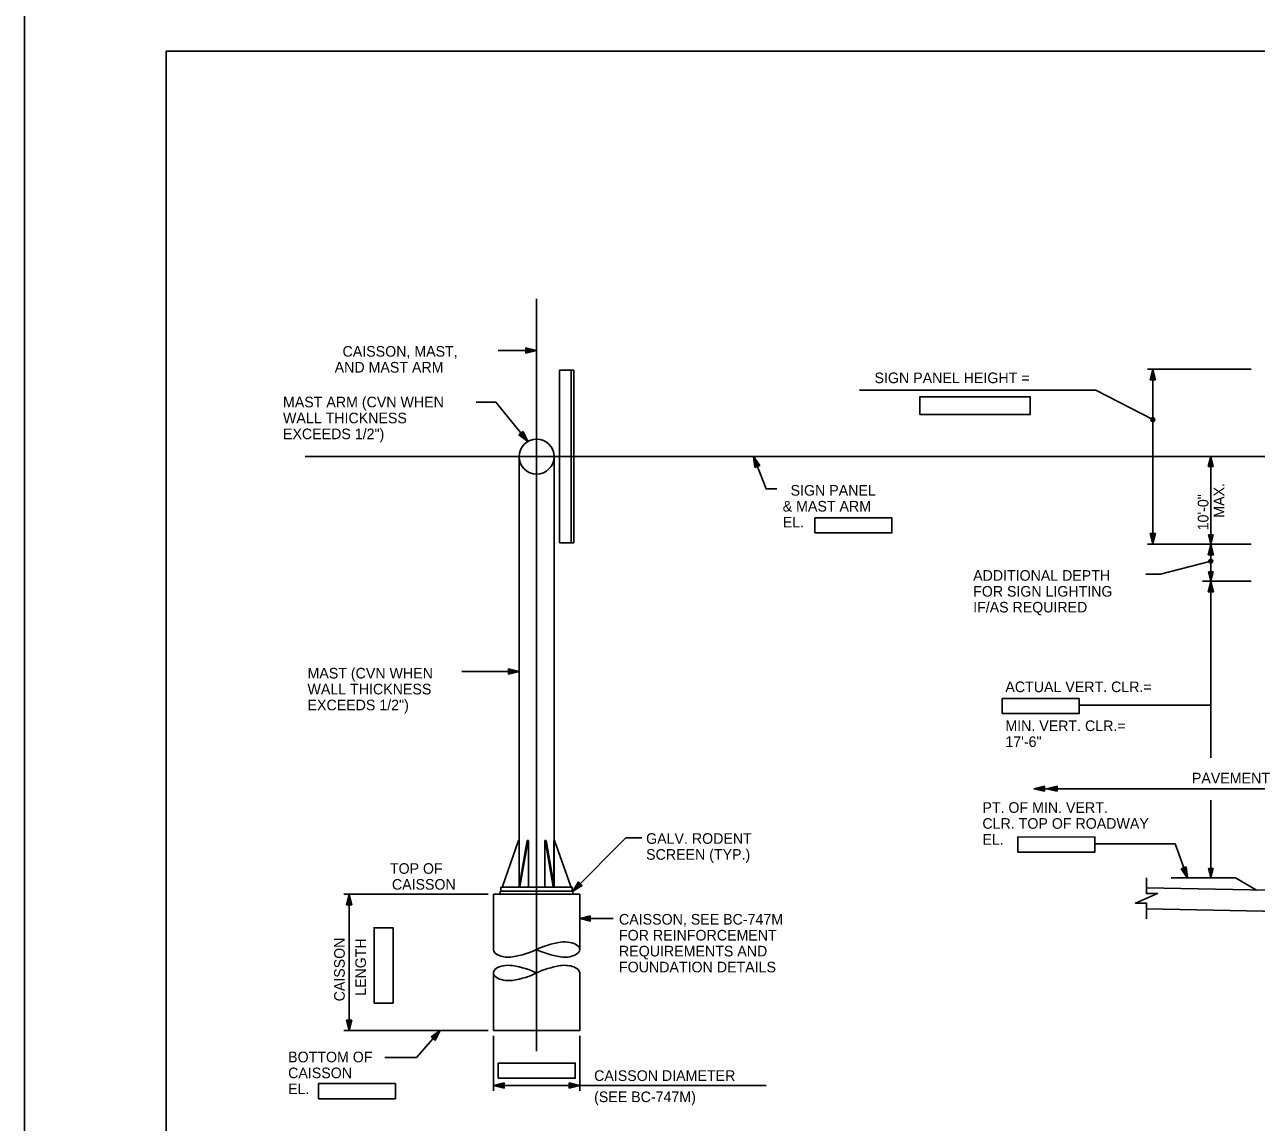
# Model space of a CAD drawing. Extents: x 640117 to 642655, y 297247 to 298435.
# Drawn here: x 640117.5 to 640465.5, y 297523.7 to 297834 of the extents above; entities that cross this region are included whole.
import ezdxf

# ---------------------------------------------------------------- set-up
doc = ezdxf.new("R2010")
doc.units = 0
for name, color, linetype in [('10', 7, 'Continuous'), ('2', 7, 'Continuous'), ('25', 7, 'Continuous'), ('49', 7, 'Continuous'), ('50', 7, 'Continuous'), ('51', 7, 'Continuous'), ('52', 7, 'Continuous'), ('55', 7, 'Continuous'), ('PLT-BNDY', 7, 'Continuous')]:
    doc.layers.add(name, color=color, linetype=linetype)

msp = doc.modelspace()

# ---------------------------------------------------------------- linework, layer by layer
at = {"layer": '10'}
for p, q in [((640452.64, 297711.85), (640452.63, 297626.7)), ((640451.97, 297689.76), (640452.63, 297687.11)), ((640453.3, 297689.76), (640451.97, 297689.76)), ((640452.17, 297689.6), (640452.63, 297687.76)), ((640453.1, 297689.6), (640452.17, 297689.6)), ((640452.37, 297689.44), (640452.63, 297688.41)), ((640452.89, 297689.44), (640452.37, 297689.44)), ((640452.55, 297689.38), (640452.63, 297689.05)), ((640452.63, 297687.11), (640453.3, 297689.76)), ((640452.63, 297687.76), (640453.1, 297689.6)), ((640452.63, 297688.41), (640452.89, 297689.44)), ((640452.63, 297689.05), (640452.71, 297689.37)), ((640451.97, 297679.28), (640452.63, 297676.63)), ((640453.3, 297679.28), (640451.97, 297679.28)), ((640452.17, 297679.12), (640452.63, 297677.28)), ((640453.1, 297679.12), (640452.17, 297679.12)), ((640452.37, 297678.96), (640452.63, 297677.92)), ((640452.89, 297678.96), (640452.37, 297678.96)), ((640452.55, 297678.9), (640452.63, 297678.57)), ((640452.63, 297676.63), (640453.3, 297679.28)), ((640452.63, 297677.28), (640453.1, 297679.12)), ((640452.63, 297677.92), (640452.89, 297678.96)), ((640452.63, 297678.57), (640452.71, 297678.88)), ((640452.63, 297641.63), (640415.43, 297641.63)), ((640452.63, 297614.72), (640452.63, 297592.74)), ((640445.7, 297595.86), (640444.27, 297595.34)), ((640444.27, 297595.34), (640446.02, 297592.74)), ((640445.55, 297595.61), (640444.55, 297595.25)), ((640444.55, 297595.25), (640445.77, 297593.44)), ((640445.39, 297595.36), (640444.83, 297595.16)), ((640444.83, 297595.16), (640445.52, 297594.14)), ((640445.05, 297595.16), (640445.26, 297594.84)), ((640445.26, 297594.84), (640445.23, 297595.21)), ((640445.52, 297594.14), (640445.39, 297595.36)), ((640445.77, 297593.44), (640445.55, 297595.61)), ((640446.02, 297592.74), (640445.7, 297595.86)), ((640451.97, 297595.39), (640452.63, 297592.74)), ((640453.29, 297595.39), (640451.97, 297595.39)), ((640452.17, 297595.23), (640452.63, 297593.39)), ((640453.09, 297595.23), (640452.17, 297595.23)), ((640452.37, 297595.07), (640452.63, 297594.03)), ((640452.89, 297595.07), (640452.37, 297595.07)), ((640452.55, 297595.01), (640452.63, 297594.68)), ((640452.63, 297592.74), (640453.29, 297595.39)), ((640452.63, 297593.39), (640453.09, 297595.23)), ((640452.63, 297594.03), (640452.89, 297595.07)), ((640452.63, 297594.68), (640452.71, 297594.99))]:
    msp.add_line(p, q, dxfattribs=at)
for points in [[(640446.02, 297592.74), (640442.53, 297602.41), (640419.7, 297602.41)], [(640441.45, 297592.74), (640459.58, 297592.74), (640465.5, 297589.31)]]:
    msp.add_lwpolyline(points, dxfattribs=at)
msp.add_lwpolyline([(640216.21, 297557.37), (640221.58, 297557.37), (640221.58, 297578.69), (640216.21, 297578.69)], close=True, dxfattribs=at)
at = {"layer": '2'}
for p, q in [((640157.46, 297262.46), (640157.46, 297826.46)), ((640157.46, 297826.46), (640943.46, 297826.46))]:
    msp.add_line(p, q, dxfattribs=at)
for points in [[(640370.43, 297723.77), (640401.59, 297723.77), (640401.59, 297728.75), (640370.43, 297728.75)], [(640340.78, 297690.26), (640362.53, 297690.26), (640362.53, 297694.51), (640340.78, 297694.51)], [(640393.68, 297639.22), (640415.43, 297639.22), (640415.43, 297643.47), (640393.68, 297643.47)], [(640398.13, 297600.08), (640419.88, 297600.07), (640419.88, 297604.32), (640398.13, 297604.33)], [(640251.3, 297536.15), (640273.05, 297536.14), (640273.05, 297540.39), (640251.3, 297540.4)], [(640200.47, 297530.35), (640222.22, 297530.35), (640222.22, 297534.6), (640200.47, 297534.6)]]:
    msp.add_lwpolyline(points, close=True, dxfattribs=at)
at = {"layer": '25'}
msp.add_line((640434.45, 297589.93), (640509.69, 297588.43), dxfattribs=at)
msp.add_lwpolyline([(640434.45, 297584.03), (640509.69, 297582.52)], dxfattribs=at)
at = {"layer": '49'}
for p, q in [((640268.61, 297687.47), (640268.61, 297736.24)), ((640268.61, 297736.24), (640272.67, 297736.24)), ((640271.86, 297687.47), (640271.86, 297736.24)), ((640272.67, 297687.47), (640272.67, 297736.24)), ((640268.61, 297687.47), (640272.67, 297687.47))]:
    msp.add_line(p, q, dxfattribs=at)
at = {"layer": '50'}
for p, q in [((640262.11, 297543.75), (640262.11, 297756.48)), ((640196.72, 297711.85), (640710.96, 297711.85))]:
    msp.add_line(p, q, dxfattribs=at)
at = {"layer": '51'}
for p, q in [((640249.91, 297588.17), (640274.3, 297588.17)), ((640249.91, 297572.51), (640249.91, 297588.17)), ((640274.3, 297572.51), (640274.3, 297588.17)), ((640249.91, 297549.58), (640249.91, 297565.89)), ((640274.3, 297549.58), (640274.3, 297565.89)), ((640249.91, 297549.58), (640274.3, 297549.58))]:
    msp.add_line(p, q, dxfattribs=at)
for centre, major_axis, start_param, end_param in [((640274.3, 297566.42), (17.24, 0), 1.89032, 2.356194), ((640269.98, 297572.51), (4.32, 0), 4.455588, 8.110783), ((640254.23, 297572.51), (-4.32, 0), 0, 1.827597), ((640249.91, 297578.61), (-17.24, 0), 1.89032, 2.356194), ((640274.3, 297578.61), (17.24, 0), 3.926991, 4.392865), ((640254.23, 297565.89), (-4.32, 0), 4.455588, 8.110783), ((640249.91, 297559.79), (-17.24, 0), 3.926991, 4.392865), ((640274.3, 297559.79), (17.24, 0), 1.89032, 2.356194), ((640269.98, 297565.89), (4.32, 0), 0, 1.827597), ((640249.91, 297571.98), (-17.24, 0), 1.89032, 2.356194)]:
    msp.add_ellipse(centre, major_axis=major_axis, ratio=0.5, start_param=start_param, end_param=end_param, dxfattribs=at)
at = {"layer": '52'}
for p, q in [((640262.11, 297741.87), (640259.11, 297742.62)), ((640259.11, 297742.62), (640259.11, 297741.12)), ((640259.11, 297741.12), (640262.11, 297741.87)), ((640261.37, 297741.87), (640259.28, 297742.39)), ((640259.28, 297742.39), (640259.28, 297741.35)), ((640259.28, 297741.35), (640261.37, 297741.87)), ((640260.64, 297741.87), (640259.46, 297742.16)), ((640259.46, 297742.16), (640259.46, 297741.57)), ((640259.46, 297741.57), (640260.64, 297741.87)), ((640259.53, 297741.78), (640259.91, 297741.87)), ((640259.91, 297741.87), (640259.55, 297741.96)), ((640464, 297736.59), (640434.76, 297736.59)), ((640436.26, 297736.59), (640435.51, 297733.59)), ((640435.51, 297733.59), (640437.01, 297733.59)), ((640436.26, 297735.85), (640435.73, 297733.76)), ((640435.73, 297733.76), (640436.78, 297733.76)), ((640436.26, 297735.12), (640435.96, 297733.94)), ((640435.96, 297733.94), (640436.55, 297733.94)), ((640436.26, 297734.39), (640436.17, 297734.03)), ((640436.26, 297687.12), (640436.26, 297736.59)), ((640437.01, 297733.59), (640436.26, 297736.59)), ((640436.78, 297733.76), (640436.26, 297735.85)), ((640436.55, 297733.94), (640436.26, 297735.12)), ((640436.35, 297734.01), (640436.26, 297734.39)), ((640258.3, 297718.92), (640257.13, 297717.98)), ((640257.13, 297717.98), (640259.6, 297716.12)), ((640258.23, 297718.64), (640257.42, 297717.98)), ((640257.42, 297717.98), (640259.14, 297716.69)), ((640258.17, 297718.36), (640257.71, 297717.99)), ((640257.71, 297717.99), (640258.68, 297717.26)), ((640257.91, 297718.06), (640258.22, 297717.83)), ((640258.22, 297717.83), (640258.06, 297718.16)), ((640258.68, 297717.26), (640258.17, 297718.36)), ((640259.14, 297716.69), (640258.23, 297718.64)), ((640259.6, 297716.12), (640258.3, 297718.92)), ((640323.41, 297711.85), (640325.2, 297709.32)), ((640323.8, 297708.78), (640323.41, 297711.85)), ((640323.68, 297711.17), (640324.92, 297709.41)), ((640323.95, 297709.03), (640323.68, 297711.17)), ((640325.2, 297709.32), (640323.8, 297708.78)), ((640324.09, 297709.28), (640323.94, 297710.48)), ((640323.94, 297710.48), (640324.64, 297709.49)), ((640324.92, 297709.41), (640323.95, 297709.03)), ((640324.64, 297709.49), (640324.09, 297709.28)), ((640324.21, 297709.8), (640324.42, 297709.5)), ((640324.26, 297709.42), (640324.21, 297709.8)), ((640452.64, 297711.85), (640451.93, 297709.04)), ((640451.93, 297709.04), (640453.34, 297709.04)), ((640452.64, 297711.16), (640452.15, 297709.2)), ((640452.15, 297709.2), (640453.13, 297709.2)), ((640452.64, 297710.48), (640452.36, 297709.37)), ((640452.36, 297709.37), (640452.91, 297709.37)), ((640452.64, 297709.79), (640452.55, 297709.46)), ((640453.34, 297709.04), (640452.64, 297711.85)), ((640453.13, 297709.2), (640452.64, 297711.16)), ((640452.91, 297709.37), (640452.64, 297710.48)), ((640452.72, 297709.44), (640452.64, 297709.79)), ((640435.51, 297690.12), (640436.26, 297687.12)), ((640437.01, 297690.12), (640435.51, 297690.12)), ((640435.73, 297689.94), (640436.26, 297687.85)), ((640436.78, 297689.94), (640435.73, 297689.94)), ((640435.96, 297689.76), (640436.26, 297688.58)), ((640436.55, 297689.76), (640435.96, 297689.76)), ((640436.16, 297689.69), (640436.26, 297689.31)), ((640436.26, 297687.12), (640437.01, 297690.12)), ((640436.26, 297687.85), (640436.78, 297689.94)), ((640436.26, 297688.58), (640436.55, 297689.76)), ((640436.26, 297689.31), (640436.35, 297689.67)), ((640464, 297687.12), (640434.76, 297687.12)), ((640452.64, 297687.12), (640451.89, 297684.12)), ((640452.64, 297686.38), (640452.11, 297684.29)), ((640452.64, 297685.65), (640452.34, 297684.47)), ((640452.34, 297684.47), (640452.93, 297684.47)), ((640452.64, 297684.92), (640452.55, 297684.56)), ((640453.39, 297684.12), (640452.64, 297687.12)), ((640453.16, 297684.29), (640452.64, 297686.38)), ((640452.93, 297684.47), (640452.64, 297685.65)), ((640452.73, 297684.54), (640452.64, 297684.92)), ((640451.89, 297684.12), (640453.39, 297684.12)), ((640452.11, 297684.29), (640453.16, 297684.29)), ((640464, 297676.63), (640450.32, 297676.63)), ((640452.64, 297676.63), (640451.89, 297673.63)), ((640452.64, 297675.9), (640452.11, 297673.81)), ((640452.64, 297675.17), (640452.34, 297673.99)), ((640452.64, 297674.43), (640452.55, 297674.08)), ((640453.38, 297673.63), (640452.64, 297676.63)), ((640453.16, 297673.81), (640452.64, 297675.9)), ((640452.93, 297673.99), (640452.64, 297675.17)), ((640452.73, 297674.06), (640452.64, 297674.43)), ((640451.89, 297673.63), (640453.38, 297673.63)), ((640452.11, 297673.81), (640453.16, 297673.81)), ((640452.34, 297673.99), (640452.93, 297673.99)), ((640257.16, 297651.09), (640254.16, 297651.84)), ((640254.16, 297651.84), (640254.16, 297650.34)), ((640254.16, 297650.34), (640257.16, 297651.09)), ((640256.43, 297651.09), (640254.34, 297651.62)), ((640254.34, 297651.62), (640254.34, 297650.57)), ((640254.34, 297650.57), (640256.43, 297651.09)), ((640255.69, 297651.09), (640254.51, 297651.39)), ((640254.51, 297651.39), (640254.51, 297650.8)), ((640254.51, 297650.8), (640255.69, 297651.09)), ((640254.58, 297651), (640254.96, 297651.09)), ((640254.96, 297651.09), (640254.6, 297651.18)), ((640405.6, 297618.73), (640402.6, 297617.98)), ((640405.42, 297618.5), (640403.33, 297617.98)), ((640405.42, 297617.46), (640405.42, 297618.5)), ((640405.6, 297617.23), (640405.6, 297618.73)), ((640409.22, 297618.73), (640406.22, 297617.98)), ((640409.04, 297618.5), (640406.95, 297617.98)), ((640409.04, 297617.46), (640409.04, 297618.5)), ((640409.22, 297617.23), (640409.22, 297618.73)), ((640402.6, 297617.98), (640489.81, 297617.98)), ((640402.6, 297617.98), (640405.6, 297617.23)), ((640403.33, 297617.98), (640405.42, 297617.46)), ((640405.24, 297618.28), (640404.06, 297617.98)), ((640404.06, 297617.98), (640405.24, 297617.68)), ((640405.17, 297618.07), (640404.8, 297617.98)), ((640404.8, 297617.98), (640405.15, 297617.89)), ((640405.24, 297617.68), (640405.24, 297618.28)), ((640406.22, 297617.98), (640409.22, 297617.23)), ((640406.95, 297617.98), (640409.04, 297617.46)), ((640408.87, 297618.28), (640407.69, 297617.98)), ((640407.69, 297617.98), (640408.87, 297617.68)), ((640408.8, 297618.07), (640408.42, 297617.98)), ((640408.42, 297617.98), (640408.78, 297617.89)), ((640408.87, 297617.68), (640408.87, 297618.28)), ((640272.35, 297588.99), (640287.36, 297604.1)), ((640273.93, 297591.64), (640272.35, 297588.99)), ((640272.35, 297588.99), (640275, 297590.59)), ((640273.97, 297591.36), (640272.87, 297589.51)), ((640272.87, 297589.51), (640274.71, 297590.62)), ((640274, 297591.07), (640273.38, 297590.03)), ((640273.38, 297590.03), (640274.42, 297590.66)), ((640274.1, 297590.88), (640273.9, 297590.55)), ((640273.9, 297590.55), (640274.21, 297590.74)), ((640275, 297590.59), (640273.93, 297591.64)), ((640274.71, 297590.62), (640273.97, 297591.36)), ((640274.42, 297590.66), (640274, 297591.07)), ((640248.41, 297588.17), (640207.63, 297588.17)), ((640209.13, 297588.17), (640208.38, 297585.17)), ((640209.13, 297587.44), (640208.61, 297585.35)), ((640209.13, 297549.58), (640209.13, 297588.17)), ((640209.88, 297585.17), (640209.13, 297588.17)), ((640209.66, 297585.35), (640209.13, 297587.44)), ((640208.38, 297585.17), (640209.88, 297585.17)), ((640208.61, 297585.35), (640209.66, 297585.35)), ((640209.13, 297586.71), (640208.84, 297585.53)), ((640208.84, 297585.53), (640209.43, 297585.53)), ((640209.13, 297585.98), (640209.04, 297585.62)), ((640209.43, 297585.53), (640209.13, 297586.71)), ((640209.23, 297585.6), (640209.13, 297585.98)), ((640277.3, 297582), (640274.3, 297581.25)), ((640274.3, 297581.25), (640277.3, 297580.5)), ((640277.12, 297581.77), (640275.03, 297581.25)), ((640275.03, 297581.25), (640277.12, 297580.73)), ((640276.94, 297581.54), (640275.76, 297581.25)), ((640275.76, 297581.25), (640276.94, 297580.95)), ((640276.87, 297581.34), (640276.5, 297581.25)), ((640276.5, 297581.25), (640276.85, 297581.16)), ((640276.94, 297580.95), (640276.94, 297581.54)), ((640277.12, 297580.73), (640277.12, 297581.77)), ((640277.3, 297580.5), (640277.3, 297582)), ((640208.38, 297552.58), (640209.13, 297549.58)), ((640209.88, 297552.58), (640208.38, 297552.58)), ((640208.61, 297552.41), (640209.13, 297550.32)), ((640209.66, 297552.41), (640208.61, 297552.41)), ((640208.84, 297552.23), (640209.13, 297551.05)), ((640209.43, 297552.23), (640208.84, 297552.23)), ((640209.13, 297549.58), (640209.88, 297552.58)), ((640209.13, 297550.32), (640209.66, 297552.41)), ((640209.13, 297551.05), (640209.43, 297552.23)), ((640248.41, 297549.58), (640207.63, 297549.58)), ((640209.04, 297552.16), (640209.13, 297551.78)), ((640209.13, 297551.78), (640209.22, 297552.14)), ((640234.9, 297549.58), (640232.34, 297547.84)), ((640234.41, 297549.04), (640232.63, 297547.82)), ((640233.41, 297547.13), (640234.41, 297549.04)), ((640233.46, 297546.84), (640234.9, 297549.58)), ((640232.34, 297547.84), (640233.46, 297546.84)), ((640232.63, 297547.82), (640233.41, 297547.13)), ((640233.92, 297548.49), (640232.92, 297547.8)), ((640232.92, 297547.8), (640233.36, 297547.41)), ((640233.44, 297547.94), (640233.13, 297547.73)), ((640233.25, 297547.6), (640233.44, 297547.94)), ((640233.36, 297547.41), (640233.92, 297548.49)), ((640249.91, 297548.08), (640249.91, 297532.55)), ((640274.3, 297548.08), (640274.3, 297532.55)), ((640252.91, 297534.8), (640249.91, 297534.05)), ((640252.91, 297533.3), (640252.91, 297534.8)), ((640274.3, 297534.05), (640271.3, 297534.8)), ((640271.3, 297534.8), (640271.3, 297533.3)), ((640274.3, 297534.05), (640249.91, 297534.05)), ((640249.91, 297534.05), (640252.91, 297533.3)), ((640252.74, 297534.57), (640250.65, 297534.05)), ((640250.65, 297534.05), (640252.74, 297533.53)), ((640252.56, 297534.35), (640251.38, 297534.05)), ((640251.38, 297534.05), (640252.56, 297533.75)), ((640252.49, 297534.14), (640252.11, 297534.05)), ((640252.11, 297534.05), (640252.47, 297533.96)), ((640252.56, 297533.75), (640252.56, 297534.35)), ((640252.74, 297533.53), (640252.74, 297534.57)), ((640271.3, 297533.3), (640274.3, 297534.05)), ((640273.56, 297534.05), (640271.47, 297534.57)), ((640271.47, 297534.57), (640271.47, 297533.53)), ((640271.47, 297533.53), (640273.56, 297534.05)), ((640272.83, 297534.05), (640271.65, 297534.35)), ((640271.65, 297534.35), (640271.65, 297533.75)), ((640271.65, 297533.75), (640272.83, 297534.05)), ((640271.72, 297533.96), (640272.1, 297534.05)), ((640272.1, 297534.05), (640271.74, 297534.14)), ((640326.99, 297534.05), (640274.3, 297534.05))]:
    msp.add_line(p, q, dxfattribs=at)
for points in [[(640262.11, 297741.87), (640251.28, 297741.87)], [(640436.26, 297722.29), (640420.12, 297730.65), (640353.4, 297730.65)], [(640259.6, 297716.12), (640250.64, 297727.21), (640245.06, 297727.21)], [(640323.41, 297711.85), (640326.95, 297702.73), (640330.04, 297702.73)], [(640452.64, 297682.33), (640438.4, 297678.62), (640434.3, 297678.62)], [(640257.16, 297651.09), (640241.01, 297651.09)], [(640287.36, 297604.1), (640291.85, 297604.1)], [(640434.45, 297581.15), (640434.45, 297585.64), (640431.33, 297585.64), (640437.57, 297588.32), (640434.45, 297588.32), (640434.45, 297592.81)], [(640274.3, 297581.25), (640283.8, 297581.25)], [(640234.9, 297549.58), (640228.17, 297542.01), (640219.28, 297542.01)]]:
    msp.add_lwpolyline(points, dxfattribs=at)
for centre, radius in [((640436.26, 297722.29), 0.536), ((640436.26, 297722.29), 0.268), ((640452.64, 297682.33), 0.536), ((640452.64, 297682.33), 0.268)]:
    msp.add_circle(centre, radius, dxfattribs=at)
at = {"layer": '55'}
for p, q in [((640257.16, 297590.16), (640257.16, 297711.85)), ((640267.05, 297590.16), (640267.05, 297711.85)), ((640252.45, 297590.36), (640257.03, 297603.36)), ((640257.23, 297603.36), (640257.03, 297603.36)), ((640257.15, 297590.36), (640259.43, 297603.36)), ((640257.23, 297590.56), (640257.23, 297603.36)), ((640257.23, 297590.16), (640257.23, 297602.04)), ((640257.41, 297590.36), (640259.7, 297603.36)), ((640259.8, 297603.36), (640259.43, 297603.36)), ((640259.8, 297590.56), (640259.8, 297603.36)), ((640264.41, 297590.56), (640264.41, 297603.36)), ((640264.41, 297603.36), (640264.78, 297603.36)), ((640266.8, 297590.36), (640264.51, 297603.36)), ((640267.06, 297590.36), (640264.78, 297603.36)), ((640266.98, 297590.56), (640266.98, 297603.36)), ((640266.98, 297603.36), (640267.18, 297603.36)), ((640266.98, 297590.16), (640266.98, 297602.04)), ((640271.76, 297590.36), (640267.18, 297603.36)), ((640257.23, 297590.56), (640256.82, 297590.16)), ((640259.8, 297590.56), (640259.6, 297590.16)), ((640264.41, 297590.56), (640264.61, 297590.16)), ((640266.98, 297590.56), (640267.39, 297590.16)), ((640251.86, 297588.99), (640272.35, 297588.99)), ((640251.86, 297588.17), (640251.86, 297588.99)), ((640252.05, 297588.99), (640252.05, 297590.16)), ((640252.05, 297590.16), (640272.16, 297590.16)), ((640252.45, 297590.16), (640252.45, 297590.36)), ((640257.15, 297590.16), (640257.15, 297590.36)), ((640257.41, 297590.16), (640257.41, 297590.36)), ((640266.8, 297590.16), (640266.8, 297590.36)), ((640267.06, 297590.16), (640267.06, 297590.36)), ((640271.76, 297590.16), (640271.76, 297590.36)), ((640272.16, 297588.99), (640272.16, 297590.16)), ((640272.35, 297588.17), (640272.35, 297588.99))]:
    msp.add_line(p, q, dxfattribs=at)
msp.add_circle((640262.11, 297711.85), 4.95, dxfattribs=at)
at = {"layer": 'PLT-BNDY'}
msp.add_lwpolyline([(640117.46, 297841.46), (640958.46, 297841.46), (640958.46, 297247.46), (640117.46, 297247.46)], close=True, dxfattribs=at)

# ---------------------------------------------------------------- texts
at = {"layer": '10'}
for s, p in [('ADDITIONAL DEPTH', (640385.49, 297676.76)), ('FOR SIGN LIGHTING', (640385.49, 297672.27)), ('IF/AS REQUIRED', (640385.49, 297667.79))]:
    msp.add_text(s, height=2.9917, dxfattribs=at).set_placement(p)
at = {"layer": '2'}
for s, height, p in [('  CAISSON, MAST,', 3, (640205.06, 297740.1)), ('AND MAST ARM', 3, (640205.06, 297735.6)), ('SIGN PANEL HEIGHT =', 3, (640357.61, 297732.61)), ('MAST ARM (CVN WHEN', 3, (640190.46, 297725.77)), ('WALL THICKNESS', 3, (640190.46, 297721.27)), ('EXCEEDS 1/2")', 3, (640190.46, 297716.77)), ('  SIGN PANEL', 3, (640331.66, 297700.82)), ('& MAST ARM', 3, (640331.66, 297696.32)), ('EL.', 3, (640331.66, 297691.82)), ('MAST (CVN WHEN', 3, (640197.39, 297649.13)), ('WALL THICKNESS', 3, (640197.39, 297644.63)), ('ACTUAL VERT. CLR.=', 3, (640394.58, 297645.27)), ('EXCEEDS 1/2")', 3, (640197.39, 297640.13)), ('MIN. VERT. CLR.=', 3, (640394.58, 297634.26)), ('17\'-6"', 3, (640394.58, 297629.76)), ('PT. OF MIN. VERT.', 3, (640388.09, 297611.15)), ('CLR. TOP OF ROADWAY', 3, (640388.09, 297606.65)), ('GALV. RODENT', 3, (640293.06, 297602.39)), ('EL.', 3, (640388.09, 297602.15)), ('SCREEN (TYP.)', 3, (640293.06, 297597.89)), ('TOP OF ', 2.992, (640220.68, 297593.92)), ('CAISSON', 2.992, (640221.25, 297589.43)), ('CAISSON, SEE BC-747M', 3, (640285.4, 297579.56)), ('FOR REINFORCEMENT', 3, (640285.4, 297575.06)), ('REQUIREMENTS AND', 3, (640285.4, 297570.56)), ('FOUNDATION DETAILS', 3, (640285.4, 297566.06)), ('BOTTOM OF', 3, (640191.91, 297540.64)), ('CAISSON', 3, (640191.91, 297536.14)), ('CAISSON DIAMETER', 3, (640278.37, 297535.37)), ('EL.', 3, (640191.91, 297531.64)), ('(SEE BC-747M)', 3, (640278.37, 297529.38))]:
    msp.add_text(s, height=height, dxfattribs=at).set_placement(p)
for s, height, p in [('MAX.', 3, (640456.46, 297694.58)), ('10\'-0"', 3, (640451.96, 297691)), ('CAISSON', 2.992, (640207.91, 297557.87)), ('LENGTH', 2.992, (640213.9, 297559.43))]:
    msp.add_text(s, height=height, rotation=90, dxfattribs=at).set_placement(p)
at = {"layer": '52'}
msp.add_text('PAVEMENT', height=3, dxfattribs=at).set_placement((640447.29, 297619.48))

doc.saveas('drawing.dxf')
